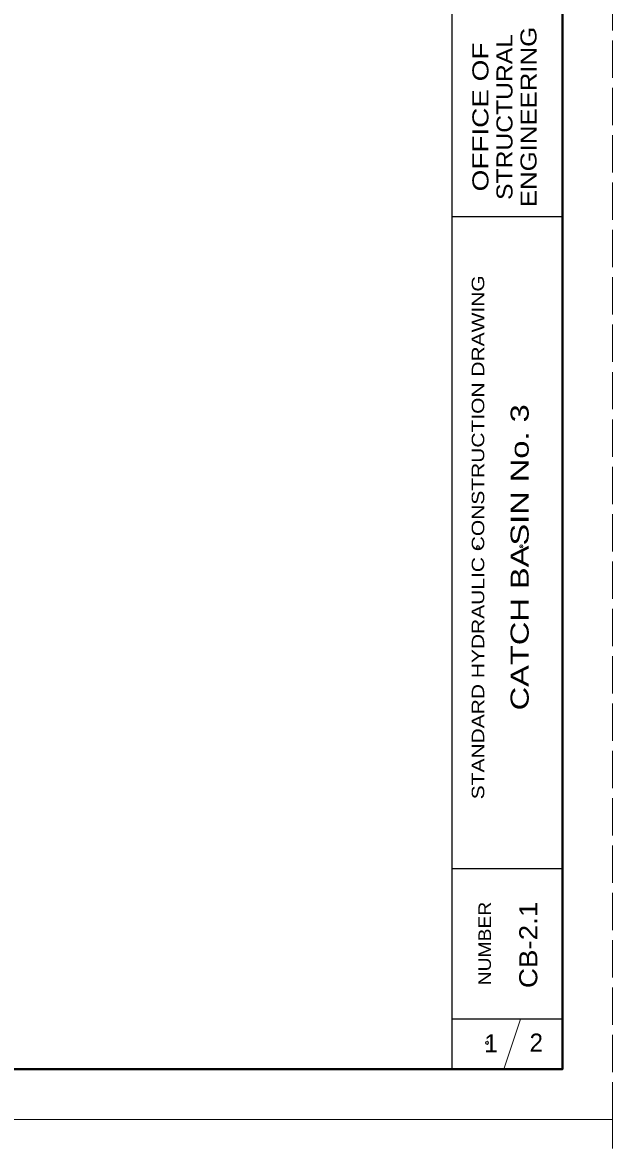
# Model space of a CAD drawing. Extents: x 1352.5 to 1386.5, y 735.9 to 779.9.
# Drawn here: x 1380.63 to 1386.51, y 757.67 to 768.86 of the extents above; entities that cross this region are included whole.
import ezdxf
from ezdxf.enums import TextEntityAlignment as Align

# ---------------------------------------------------------------- set-up
doc = ezdxf.new("R2010")
doc.units = 0
doc.header["$LTSCALE"] = 0.062
doc.header["$PDMODE"] = 32
doc.header["$PDSIZE"] = 0.031
doc.linetypes.add('LONG_DASHED', pattern=[7.5, 6, -1.5])
doc.layers.add('1', color=7, linetype='Continuous', lineweight=13)

msp = doc.modelspace()

# ---------------------------------------------------------------- linework, layer by layer
at = {"layer": '1', "lineweight": 25}
for p, q in [((1384.913, 758.41967), (1384.913, 779.41967)), ((1386.013, 779.41967), (1386.013, 758.41967)), ((1386.013, 766.91967), (1384.913, 766.91967)), ((1386.013, 760.41967), (1384.913, 760.41967)), ((1386.013, 758.91967), (1384.913, 758.91967))]:
    msp.add_line(p, q, dxfattribs=at)
at = {"layer": '1'}
msp.add_line((1385.42967, 758.41967), (1385.59633, 758.91967), dxfattribs=at)
at = {"layer": '1', "linetype": 'LONG_DASHED'}
for points in [[(1352.513, 757.91967), (1386.513, 757.91967), (1386.513, 779.91967), (1352.513, 779.91967)], [(1352.513, 735.91967), (1386.513, 735.91967), (1386.513, 757.91967), (1352.513, 757.91967)]]:
    msp.add_lwpolyline(points, close=True, dxfattribs=at)
at = {"layer": '1', "lineweight": 25}
msp.add_lwpolyline([(1386.013, 758.41967), (1354.513, 758.41967), (1354.513, 779.41967)], dxfattribs=at)
at = {"layer": '1', "lineweight": 40}
msp.add_lwpolyline([(1354.513, 779.41967), (1386.013, 779.41967), (1386.013, 758.41967), (1354.513, 758.41967)], close=True, dxfattribs=at)
msp.add_lwpolyline([(1354.513, 779.41967), (1386.013, 779.41967), (1386.013, 758.41967), (1354.513, 758.41967)], close=True, dxfattribs=at)
at = {"layer": '1'}
for p in [(1385.17042, 763.62567), (1385.60325, 763.633), (1385.26108, 758.68342)]:
    msp.add_point(p, dxfattribs=at)

# ---------------------------------------------------------------- texts
for s, height, width, p in [('ENGINEERING', 0.16, 1.2, (1385.75475, 767.91421)), ('STRUCTURAL', 0.16, 1.15, (1385.51475, 767.91413)), ('OFFICE OF', 0.16, 1.3, (1385.27475, 767.91413)), ('STANDARD HYDRAULIC CONSTRUCTION DRAWING', 0.125, 1.25, (1385.23292, 763.72371)), ('CATCH BASIN No. 3', 0.18, 1.35, (1385.67617, 763.52396)), ('NUMBER', 0.125, 1.15, (1385.3, 759.67375)), ('CB-2.1', 0.18, 1.15, (1385.76233, 759.66004))]:
    msp.add_text(s, height=height, rotation=90, dxfattribs=dict(at, width=width)).set_placement(p, align=Align.CENTER)
for s, p in [('1', (1385.30085, 758.58975)), ('2', (1385.75221, 758.59633))]:
    msp.add_text(s, height=0.18, dxfattribs=at).set_placement(p, align=Align.CENTER)

doc.saveas('drawing.dxf')
